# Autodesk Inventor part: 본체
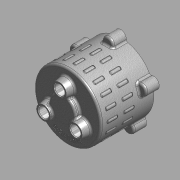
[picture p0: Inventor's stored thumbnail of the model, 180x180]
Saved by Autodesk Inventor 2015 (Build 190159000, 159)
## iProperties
Created: 2015-11
Part Number: 본체
Document SubType Name: 모델링
Designer: mdu
Material: 알루미늄 6061
Density: 1 g/cm^3
Appearance: 알루미늄 - 평지
변환 표준: STEP AP214IS
파일 이름: C:\Users\SeoGD\Desktop\?쒗뿕\紐몄껜.stp
전처리기: Build: 253, Release: 2010 SP1 - Date: Wed 07/29/2009
전송 단위: 밀리미터
불확실성: 0.01
Author: mdu
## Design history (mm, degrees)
sketch "스케치2"
  geometry: C1 r 50 at (0, 0); 1 further point
  constraints: 1 centre point, 1 coincident
  dimensions: "d9" = 100 diameter of C1
extrude "돌출2" new body sketch "스케치2" distance "d10" = 80; taper "d11" = 0 deg
feature "쉘1" dims "d12" = 5
sketch "스케치3" dims "d13" = 55
  geometry: C1 r 7.5 at (0, 27.5); C2 r 12.5 at (0, 27.5); 2 further points
  constraints: 2 centre point, 2 coincident, 2 vertical alignment, 2 other
  dimensions: "d14" = 15 diameter of C1; "d15" = 25 diameter of C2
extrude "돌출3" join sketch "스케치3" distance "d16" = 12; taper "d17" = -10 deg
hole "구멍2" diameter "d20" = 15; stored, may be unused: countersink angle "d24" = 90 deg, drill point angle "d26" = 118 deg; dims "d18" = 10, "d19" = 10, "d21" = 6, "d22" = 4, "d23" = 2, "d25" = 15
chamfer "모따기1" distance "d27" = 1; stored, may be unused: second distance "d28" = 2, angle "d29" = 45 deg
sketch "스케치4"
  geometry: L1 (0, 0)-(0, 88); L2 (0, 70)-(13.16, 70); L3 (-45, 75)-(45, 75) reference; L4 (-50, 80)-(50, 80) reference; L5 (13.16, 70)-(14.5, 75); L6 (20, 80)-(20, 88); L7 (20, 88)-(0, 88); L8 (20, 80)-(14.5, 75)
  constraints: 12 end point, 3 point on line, 2 perpendicular, 1 vertical
  dimensions: "d34" = 40 diameter of L6 L1; "d35" = 105 deg angle of L5 L3; "d36" = 5 distance between parallel lines of L2 L3; "d37" = 8 distance between parallel lines of L7 L4; "d51" = 29 diameter of L5.end L1
revolve "회전1" sketch "스케치4" stored, may be unused: angle "d38" = 90 deg
hole "구멍3" diameter "d41" = 15; stored, may be unused: countersink angle "d45" = 90 deg, drill point angle "d47" = 0 deg; dims "d39" = 10, "d40" = 10, "d42" = 6, "d43" = 22, "d44" = 13, "d46" = 15
chamfer "모따기2" distance "d48" = 1; stored, may be unused: second distance "d49" = 2, angle "d50" = 45 deg
fillet "모깎기1" dims "d52" = 3
fillet "모깎기2" dims "d53" = 3, "d72" = 0.2
sketch "스케치5"
  geometry: A1 r 50 centre (0, 0) between (50, 0) and (-8.074, 49.344) reference; A2 r 8.5 centre (0, 52) between (8.074, 49.344) and (-8.074, 49.344); 1 further point
  constraints: 5 point on circle, 1 centre point, 1 horizontal alignment
  dimensions: "d54" = 90 deg dimension on point (0, 0) A2.centre A1.start; "d55" = 52 distance of A2.centre point (0, 0); "d56" = 17 diameter of A2
extrude "돌출4" join sketch "스케치5" distance "d57" = 20; taper "d58" = 0 deg
fillet "모깎기3" dims "d59" = 3
hole "구멍4" diameter "d62" = 4.134; stored, may be unused: countersink angle "d66" = 90 deg, drill point angle "d68" = 118 deg; dims "d60" = 10, "d61" = 10, "d63" = 12, "d64" = 22, "d65" = 13, "d67" = 15
sketch "스케치6"
  geometry: C1 r 47 at (0, 0) reference; C2 r 42.5 at (0, 0); 1 further point
  constraints: 1 centre point, 1 coincident, 1 other
  dimensions: "d73" = 85 diameter of C2
feature "엠보싱1" sketch "스케치6" dims "d74" = 0.5, "d75" = 0
node "작업 평면1"
sketch "스케치7"
  geometry: A1 r 50 centre (0, 0) between (5.144, 49.735) and (-5.144, 49.735) reference; A2 r 3 centre (0, 47.916) between (2.204, 49.951) and (-2.204, 49.951); 1 further point
  constraints: 4 point on circle, 1 centre point, 1 vertical alignment
  dimensions: "d77" = 3 radius of A2
extrude "돌출5" join sketch "스케치7" distance "d79" = 15; taper "d80" = 0 deg
fillet "모깎기4" dims "d81" = 1
fillet "모깎기5" dims "d82" = 1
node "솔리드1"
node "솔리드 본체"
node "곡면 본체"
pattern_circular "원형 패턴1" dims "d31" = 360 deg
pattern_circular "원형 패턴2" dims "d70" = 360 deg
pattern_circular "원형 패턴3" dims "d84" = 360 deg
pattern_linear "직사각형 패턴1" dims "d89" = 25
node "솔리드2"
